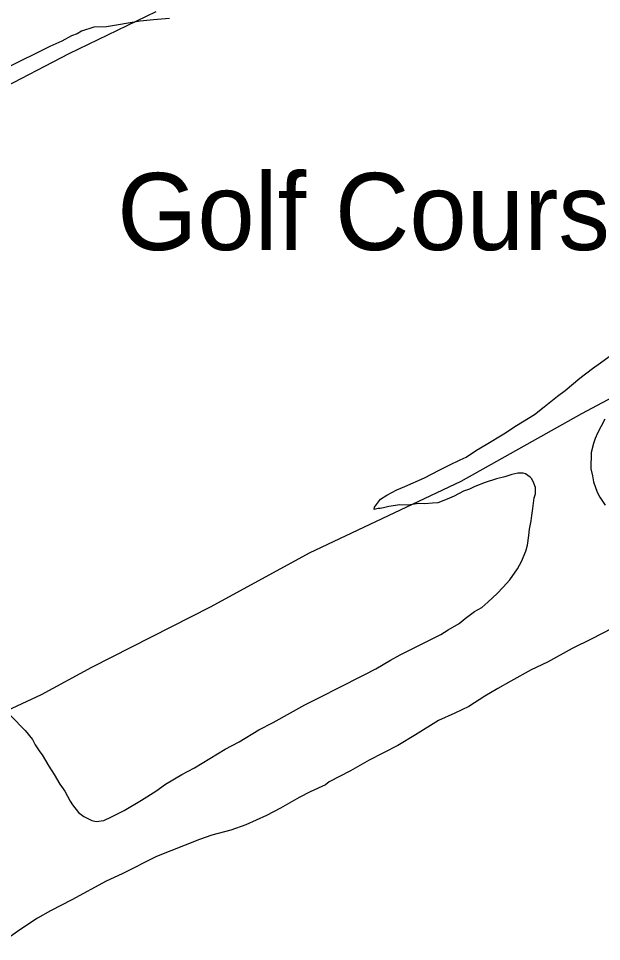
# Model space of a CAD drawing. Extents: x 3567028 to 3605064, y 510945 to 536587.
# Drawn here: x 3571875 to 3572503, y 531163 to 532157 of the extents above; entities that cross this region are included whole.
import ezdxf

# ---------------------------------------------------------------- set-up
doc = ezdxf.new("R2010")
doc.units = 0
for name, color, linetype in [('V-SITE-OTLN', 7, 'Continuous'), ('V-SITE-OTLN-IDEN', 7, 'Continuous'), ('V-SITE-VEGE', 7, 'Continuous')]:
    doc.layers.add(name, color=color, linetype=linetype)

msp = doc.modelspace()

# ---------------------------------------------------------------- linework, layer by layer
at = {"layer": 'V-SITE-OTLN'}
for p, q in [((3571929.46, 532118.99), (3572023.12, 532164.24)), ((3571780.33, 532041.34), (3571929.46, 532118.99)), ((3572583.87, 531786.22), (3572480.97, 531731.22)), ((3572480.97, 531731.22), (3572351.29, 531658.42)), ((3572351.29, 531658.42), (3572187.92, 531580.99)), ((3572187.92, 531580.99), (3572081.81, 531523.27)), ((3572081.81, 531523.27), (3571953.43, 531457.97)), ((3571953.43, 531457.97), (3571899.19, 531428.73)), ((3571899.19, 531428.73), (3571816.71, 531390.03))]:
    msp.add_line(p, q, dxfattribs=at)
at = {"layer": 'V-SITE-VEGE'}
for p, q in [((3572005.75, 532153.73), (3571969.52, 532147.85)), ((3572020.35, 532155.26), (3572005.75, 532153.73)), ((3572037.28, 532156.76), (3572020.35, 532155.26)), ((3571942.63, 532143), (3571937.93, 532140.16)), ((3571956.11, 532147.47), (3571942.63, 532143)), ((3571969.52, 532147.85), (3571956.11, 532147.47)), ((3571921.48, 532132.24), (3571908.58, 532126.6)), ((3571932.06, 532137.92), (3571921.48, 532132.24)), ((3571937.93, 532140.16), (3571932.06, 532137.92)), ((3571908.58, 532126.6), (3571861.59, 532103.4)), ((3572501.67, 531786.07), (3572518.76, 531798.65)), ((3572492.83, 531779.79), (3572501.67, 531786.07)), ((3572479.27, 531769.5), (3572492.83, 531779.79)), ((3572463.33, 531756.33), (3572479.27, 531769.5)), ((3572455.08, 531750.04), (3572463.33, 531756.33)), ((3572440.92, 531738.59), (3572455.08, 531750.04)), ((3572430.3, 531730.58), (3572440.92, 531738.59)), ((3572410.89, 531718.63), (3572430.3, 531730.58)), ((3572506.01, 531725.38), (3572498.21, 531710.34)), ((3572397.34, 531709.5), (3572410.89, 531718.63)), ((3572378.52, 531698.12), (3572397.34, 531709.5)), ((3572495.8, 531704.54), (3572493.97, 531699.32)), ((3572498.21, 531710.34), (3572495.8, 531704.54)), ((3572367.93, 531691.86), (3572378.52, 531698.12)), ((3572493.97, 531699.32), (3572491.49, 531689.45)), ((3572356.74, 531684.45), (3572367.93, 531691.86)), ((3572491.49, 531689.45), (3572491.23, 531671.96)), ((3572327.97, 531670.31), (3572338.55, 531675.98)), ((3572338.55, 531675.98), (3572350.29, 531681.63)), ((3572350.29, 531681.63), (3572356.74, 531684.45)), ((3572312.11, 531662.38), (3572327.97, 531670.31)), ((3572406.02, 531665.65), (3572398.41, 531663.43)), ((3572412.46, 531667.3), (3572406.02, 531665.65)), ((3572418.29, 531667.21), (3572412.46, 531667.3)), ((3572420.61, 531666.6), (3572418.29, 531667.21)), ((3572425.8, 531663.02), (3572420.61, 531666.6)), ((3572491.23, 531671.96), (3572492.87, 531664.36)), ((3572290.98, 531652.78), (3572312.11, 531662.38)), ((3572377.33, 531657.33), (3572366.18, 531652.83)), ((3572389.63, 531661.23), (3572377.33, 531657.33)), ((3572398.41, 531663.43), (3572389.63, 531661.23)), ((3572427.53, 531661.25), (3572425.8, 531663.02)), ((3572429.79, 531656.55), (3572427.53, 531661.25)), ((3572431.47, 531651.86), (3572429.79, 531656.55)), ((3572492.87, 531664.36), (3572493.94, 531657.93)), ((3572493.94, 531657.93), (3572497.85, 531646.8)), ((3572271.6, 531643.74), (3572282.19, 531649.41)), ((3572282.19, 531649.41), (3572290.98, 531652.78)), ((3572353.87, 531647.77), (3572343.88, 531642.67)), ((3572360.31, 531650), (3572353.87, 531647.77)), ((3572366.18, 531652.83), (3572360.31, 531650)), ((3572430.14, 531640.81), (3572431.36, 531644.87)), ((3572431.36, 531644.87), (3572431.47, 531651.86)), ((3572497.85, 531646.8), (3572500.69, 531641.51)), ((3572258, 531630.54), (3572264.54, 531639.18)), ((3572264.54, 531639.18), (3572271.6, 531643.74)), ((3572320.45, 531634.85), (3572312.28, 531634.39)), ((3572326.28, 531635.35), (3572320.45, 531634.85)), ((3572336.25, 531639.29), (3572326.28, 531635.35)), ((3572343.88, 531642.67), (3572336.25, 531639.29)), ((3572428.8, 531629.17), (3572430.14, 531640.81)), ((3572500.69, 531641.51), (3572506.39, 531632.68)), ((3572257.96, 531628.2), (3572258, 531630.54)), ((3572262.06, 531629.31), (3572257.96, 531628.2)), ((3572264.39, 531629.27), (3572262.06, 531629.31)), ((3572267.9, 531629.8), (3572264.39, 531629.27)), ((3572273.75, 531631.47), (3572267.9, 531629.8)), ((3572285.44, 531633.04), (3572273.75, 531631.47)), ((3572294.18, 531632.91), (3572285.44, 531633.04)), ((3572305.86, 531634.49), (3572294.18, 531632.91)), ((3572312.28, 531634.39), (3572305.86, 531634.49)), ((3572427.52, 531621.61), (3572428.8, 531629.17)), ((3572424.97, 531607.07), (3572426.85, 531615.78)), ((3572426.85, 531615.78), (3572427.52, 531621.61)), ((3572424.29, 531600.08), (3572424.97, 531607.07)), ((3572422.96, 531589.61), (3572424.29, 531600.08)), ((3572421.12, 531583.22), (3572422.96, 531589.61)), ((3572416.29, 531572.22), (3572421.12, 531583.22)), ((3572412.09, 531564.12), (3572416.29, 531572.22)), ((3572403.76, 531552.58), (3572412.09, 531564.12)), ((3572396.64, 531544.53), (3572403.76, 531552.58)), ((3572380.08, 531528.45), (3572390.13, 531537.62)), ((3572390.13, 531537.62), (3572396.64, 531544.53)), ((3572373.58, 531522.72), (3572380.08, 531528.45)), ((3572355.91, 531510.73), (3572365.94, 531518.16)), ((3572365.94, 531518.16), (3572373.58, 531522.72)), ((3572349.43, 531505.58), (3572355.91, 531510.73)), ((3572524.98, 531505.86), (3572492.08, 531488.86)), ((3572329.43, 531493.64), (3572337.66, 531498.76)), ((3572337.66, 531498.76), (3572349.43, 531505.58)), ((3572302.41, 531480.05), (3572329.43, 531493.64)), ((3572492.08, 531488.86), (3572470.94, 531478.68)), ((3572285.96, 531471.55), (3572302.41, 531480.05)), ((3572470.94, 531478.68), (3572444.48, 531463.92)), ((3572275.38, 531465.87), (3572285.96, 531471.55)), ((3572247.75, 531450.54), (3572259.5, 531456.78)), ((3572259.5, 531456.78), (3572275.38, 531465.87)), ((3572444.48, 531463.92), (3572426.87, 531455.43)), ((3572217.21, 531435.26), (3572247.75, 531450.54)), ((3572426.87, 531455.43), (3572405.12, 531443.51)), ((3572405.12, 531443.51), (3572391.01, 531435.56)), ((3572183.13, 531417.69), (3572203.11, 531427.88)), ((3572203.11, 531427.88), (3572217.21, 531435.26)), ((3572376.89, 531427.03), (3572359.83, 531416.2)), ((3572391.01, 531435.56), (3572376.89, 531427.03)), ((3571851.47, 531421.44), (3571881.9, 531390.1)), ((3572149.04, 531398.96), (3572183.13, 531417.69)), ((3572344.56, 531408.85), (3572326.95, 531400.95)), ((3572359.83, 531416.2), (3572344.56, 531408.85)), ((3572133.77, 531391.02), (3572149.04, 531398.96)), ((3572326.95, 531400.95), (3572302.24, 531385.58)), ((3571881.9, 531390.1), (3571889.92, 531380.65)), ((3572112.58, 531377.93), (3572133.77, 531391.02)), ((3571889.92, 531380.65), (3571892.75, 531374.78)), ((3572097.31, 531369.99), (3572112.58, 531377.93)), ((3572302.24, 531385.58), (3572283.41, 531374.2)), ((3571892.75, 531374.78), (3571897.88, 531367.12)), ((3571897.88, 531367.12), (3571900.17, 531364.17)), ((3572064.37, 531350.08), (3572097.31, 531369.99)), ((3572283.41, 531374.2), (3572252.28, 531358.34)), ((3571900.17, 531364.17), (3571907.57, 531351.82)), ((3572252.28, 531358.34), (3572232.29, 531346.97)), ((3571907.57, 531351.82), (3571913.26, 531342.99)), ((3572050.85, 531342.7), (3572064.37, 531350.08)), ((3572232.29, 531346.97), (3572209.38, 531335.07)), ((3571913.26, 531342.99), (3571919.52, 531332.4)), ((3572033.21, 531332.47), (3572050.85, 531342.7)), ((3571919.52, 531332.4), (3571924.65, 531324.75)), ((3572022.6, 531325.04), (3572033.21, 531332.47)), ((3572205.24, 531331.63), (3572188.81, 531324.3)), ((3572209.38, 531335.07), (3572205.24, 531331.63)), ((3571924.65, 531324.75), (3571930.33, 531314.17)), ((3572007.3, 531315.36), (3572022.6, 531325.04)), ((3572177.06, 531318.06), (3572157.07, 531306.69)), ((3572188.81, 531324.3), (3572177.06, 531318.06)), ((3571930.33, 531314.17), (3571933.18, 531310.05)), ((3571933.18, 531310.05), (3571939.47, 531301.79)), ((3571988.48, 531303.98), (3572007.3, 531315.36)), ((3571939.47, 531301.79), (3571945.24, 531297.62)), ((3571945.24, 531297.62), (3571953.92, 531293.42)), ((3571966.75, 531293.23), (3571974.97, 531297.19)), ((3571974.97, 531297.19), (3571988.48, 531303.98)), ((3572141.79, 531298.76), (3572119.49, 531288.6)), ((3572157.07, 531306.69), (3572141.79, 531298.76)), ((3571953.92, 531293.42), (3571958.57, 531292.18)), ((3571958.57, 531292.18), (3571966.75, 531293.23)), ((3572119.49, 531288.6), (3572103.66, 531283)), ((3572083.18, 531277.48), (3572069.7, 531273.01)), ((3572103.66, 531283), (3572083.18, 531277.48)), ((3572069.7, 531273.01), (3572023.37, 531254.46)), ((3572023.37, 531254.46), (3571986.36, 531235.77)), ((3571969.34, 531227.86), (3571932.32, 531208.01)), ((3571986.36, 531235.77), (3571969.34, 531227.86)), ((3571932.32, 531208.01), (3571909.4, 531196.11)), ((3571895.29, 531188.15), (3571876.45, 531175.61)), ((3571909.4, 531196.11), (3571895.29, 531188.15)), ((3571876.45, 531175.61), (3571858.77, 531163.05))]:
    msp.add_line(p, q, dxfattribs=at)

# ---------------------------------------------------------------- texts
at = {"layer": 'V-SITE-OTLN-IDEN'}
msp.add_text('Golf Course', height=82.9998, dxfattribs=at).set_placement((3571981.16, 531907.45))

doc.saveas('drawing.dxf')
